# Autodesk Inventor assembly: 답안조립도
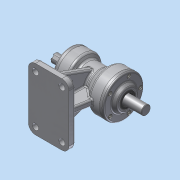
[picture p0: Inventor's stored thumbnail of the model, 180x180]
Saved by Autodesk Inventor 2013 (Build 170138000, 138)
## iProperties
Created: 2015-08
Part Number: 답안조립도
Document SubType Name: Assembly
Designer: Administrator
Author: Administrator
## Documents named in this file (10)
- C:\Users\Administrator\Desktop\450806V1037\답안조립도.iam
- C:\Users\Administrator\Desktop\450806V1037\M4x0.5.ipt
- C:\Users\Administrator\Desktop\450806V1037\뒤커버.ipt
- C:\Users\Administrator\Desktop\450806V1037\베어링 6203.ipt
- C:\Users\Administrator\Desktop\450806V1037\베어링 6205.ipt
- C:\Users\Administrator\Desktop\450806V1037\본체.ipt
- C:\Users\Administrator\Desktop\450806V1037\앞커버.ipt
- C:\Users\Administrator\Desktop\450806V1037\오일실 .ipt
- 오일실 .ipt
- C:\Users\Administrator\Desktop\450806V1037\축.ipt
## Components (10 placed, 1 different names)
1. M4x0.5:2
2. M4x0.5:3
3. M4x0.5:4
4. M4x0.5:5
5. M4x0.5:6
6. M4x0.5:1
7. M4x0.5:7
8. M4x0.5:8
9. M4x0.5:9
10. M4x0.5:10
